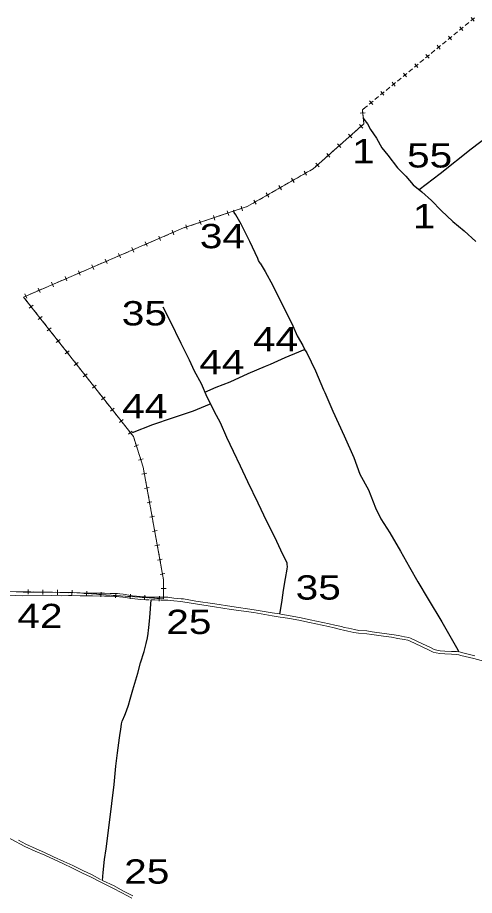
# Model space of a CAD drawing. Extents: x 476989 to 498418, y 4381813 to 4416555.
# Drawn here: x 484730 to 485670, y 4387137 to 4388943 of the extents above; entities that cross this region are included whole.
import ezdxf
from ezdxf.enums import TextEntityAlignment as Align

# ---------------------------------------------------------------- set-up
doc = ezdxf.new("R2010")
doc.units = 0
doc.header["$LTSCALE"] = 20
for name, color, linetype, lineweight in [('13', 7, 'Continuous', 13), ('34', 7, 'Continuous', 13), ('36', 7, 'Continuous', 13), ('6', 7, 'Continuous', 25)]:
    doc.layers.add(name, color=color, linetype=linetype, lineweight=lineweight)

msp = doc.modelspace()

# ---------------------------------------------------------------- linework, layer by layer
at = {"layer": '34'}
for p, q in [((485661.86, 4388935.9), (485669.59, 4388942.24)), ((485662.56, 4388942.93), (485668.9, 4388935.2)), ((485638.68, 4388916.87), (485646.41, 4388923.22)), ((485639.37, 4388923.91), (485645.72, 4388916.18)), ((485650.28, 4388926.39), (485658.01, 4388932.73)), ((485615.5, 4388897.85), (485623.23, 4388904.19)), ((485616.19, 4388904.88), (485622.54, 4388897.15)), ((485627.09, 4388907.36), (485634.82, 4388913.71)), ((485592.32, 4388878.82), (485600.05, 4388885.16)), ((485593.01, 4388885.86), (485599.35, 4388878.13)), ((485603.91, 4388888.34), (485611.64, 4388894.68)), ((485569.13, 4388859.8), (485576.86, 4388866.14)), ((485569.83, 4388866.83), (485576.17, 4388859.1)), ((485580.73, 4388869.31), (485588.46, 4388875.66)), ((485545.95, 4388840.77), (485553.68, 4388847.11)), ((485546.64, 4388847.81), (485552.99, 4388840.08)), ((485557.55, 4388850.29), (485565.28, 4388856.63)), ((485522.77, 4388821.75), (485530.5, 4388828.09)), ((485523.46, 4388828.78), (485529.8, 4388821.05)), ((485534.36, 4388831.26), (485542.09, 4388837.6)), ((485511.18, 4388812.24), (485518.91, 4388818.58)), ((485488, 4388793.21), (485495.73, 4388799.55)), ((485499.58, 4388802.72), (485507.31, 4388809.06)), ((485500.28, 4388809.76), (485506.62, 4388802.03)), ((485464.81, 4388774.19), (485472.54, 4388780.53)), ((485476.4, 4388783.69), (485484.13, 4388790.04)), ((485477.09, 4388790.73), (485483.44, 4388783)), ((485441.63, 4388755.16), (485444.8, 4388757.76)), ((485444.8, 4388757.76), (485449.36, 4388761.5)), ((485453.22, 4388764.67), (485460.95, 4388771.01)), ((485453.91, 4388771.71), (485460.26, 4388763.98)), ((485434.71, 4388745.92), (485444.65, 4388746.95)), ((485440.19, 4388741.47), (485439.16, 4388751.41)), ((485432.69, 4388715.76), (485440.18, 4388722.39)), ((485433.12, 4388722.82), (485439.75, 4388715.33)), ((485441.74, 4388726.56), (485440.71, 4388736.5)), ((485410.23, 4388695.89), (485417.72, 4388702.52)), ((485410.66, 4388702.95), (485417.28, 4388695.46)), ((485421.46, 4388705.83), (485428.95, 4388712.46)), ((485399, 4388685.96), (485406.49, 4388692.59)), ((485376.54, 4388666.09), (485384.03, 4388672.72)), ((485387.76, 4388676.02), (485395.25, 4388682.65)), ((485388.2, 4388683.08), (485394.82, 4388675.59)), ((485354.07, 4388646.22), (485361.56, 4388652.85)), ((485365.3, 4388656.15), (485372.79, 4388662.78)), ((485365.73, 4388663.21), (485372.36, 4388655.72)), ((485342.84, 4388636.28), (485350.33, 4388642.91)), ((485343.27, 4388643.34), (485349.9, 4388635.85)), ((485293.42, 4388612.2), (485298.4, 4388603.52)), ((485304.59, 4388612.84), (485313.26, 4388617.81)), ((485317.59, 4388620.29), (485326.26, 4388625.27)), ((485319.44, 4388627.12), (485324.41, 4388618.44)), ((485265.56, 4388590.45), (485274.23, 4388595.43)), ((485267.41, 4388597.28), (485272.38, 4388588.6)), ((485278.57, 4388597.92), (485287.25, 4388602.89)), ((485291.58, 4388605.37), (485300.25, 4388610.35)), ((485239.54, 4388575.53), (485248.22, 4388580.51)), ((485241.39, 4388582.36), (485246.37, 4388573.68)), ((485252.56, 4388583), (485261.23, 4388587.97)), ((485213.53, 4388560.61), (485222.2, 4388565.59)), ((485215.38, 4388567.44), (485220.35, 4388558.76)), ((485226.54, 4388568.08), (485235.22, 4388573.05)), ((485157.74, 4388539.13), (485167.22, 4388542.32)), ((485160.89, 4388545.47), (485164.07, 4388535.99)), ((485171.96, 4388543.91), (485181.44, 4388547.09)), ((485186.17, 4388548.68), (485195.65, 4388551.87)), ((485189.32, 4388555.02), (485192.5, 4388545.54)), ((485100.88, 4388520.04), (485110.36, 4388523.22)), ((485104.03, 4388526.37), (485107.21, 4388516.89)), ((485115.1, 4388524.81), (485124.58, 4388528)), ((485129.31, 4388529.59), (485138.79, 4388532.77)), ((485132.46, 4388535.92), (485135.64, 4388526.44)), ((485143.53, 4388534.36), (485153.01, 4388537.55)), ((485047.48, 4388505.3), (485051.45, 4388496.11)), ((485058.65, 4388504.67), (485067.83, 4388508.63)), ((485072.45, 4388510.49), (485081.93, 4388513.67)), ((485075.6, 4388516.82), (485078.79, 4388507.34)), ((485086.67, 4388515.26), (485096.15, 4388518.45)), ((485003.58, 4388480.9), (485012.76, 4388484.86)), ((485017.34, 4388486.84), (485026.52, 4388490.8)), ((485019.95, 4388493.41), (485023.91, 4388484.23)), ((485031.11, 4388492.78), (485040.29, 4388496.75)), ((485044.87, 4388498.72), (485054.05, 4388502.69)), ((484962.27, 4388463.07), (484971.45, 4388467.03)), ((484964.88, 4388469.64), (484968.84, 4388460.46)), ((484976.04, 4388469.01), (484985.22, 4388472.98)), ((484989.8, 4388474.95), (484998.99, 4388478.92)), ((484992.41, 4388481.53), (484996.38, 4388472.35)), ((484920.97, 4388445.25), (484930.15, 4388449.21)), ((484934.73, 4388451.19), (484943.92, 4388455.15)), ((484937.34, 4388457.76), (484941.31, 4388448.58)), ((484948.51, 4388457.13), (484957.69, 4388461.09)), ((484879.66, 4388427.42), (484888.85, 4388431.38)), ((484882.27, 4388433.99), (484886.24, 4388424.81)), ((484893.44, 4388433.36), (484902.62, 4388437.32)), ((484907.2, 4388439.3), (484916.38, 4388443.26)), ((484909.81, 4388445.87), (484913.77, 4388436.69)), ((484838.37, 4388409.59), (484847.55, 4388413.56)), ((484852.13, 4388415.53), (484861.31, 4388419.5)), ((484854.74, 4388422.11), (484858.7, 4388412.92)), ((484865.9, 4388421.48), (484875.08, 4388425.44)), ((484797.06, 4388391.76), (484806.24, 4388395.73)), ((484799.67, 4388398.34), (484803.63, 4388389.16)), ((484810.83, 4388397.71), (484820.01, 4388401.67)), ((484824.6, 4388403.65), (484833.78, 4388407.61)), ((484827.2, 4388410.22), (484831.17, 4388401.04)), ((484755.76, 4388373.94), (484764.94, 4388377.9)), ((484769.53, 4388379.88), (484778.71, 4388383.84)), ((484772.13, 4388386.45), (484776.1, 4388377.27)), ((484783.3, 4388385.82), (484792.48, 4388389.79)), ((484742, 4388368), (484751.17, 4388371.96)), ((484744.6, 4388374.57), (484748.56, 4388365.39)), ((484745.09, 4388364.07), (484751.28, 4388356.22)), ((484753.54, 4388345.27), (484761.39, 4388351.45)), ((484754.37, 4388352.29), (484760.56, 4388344.43)), ((484763.65, 4388340.5), (484769.84, 4388332.65)), ((484772.1, 4388321.7), (484779.95, 4388327.88)), ((484772.93, 4388328.72), (484779.12, 4388320.86)), ((484782.21, 4388316.93), (484788.4, 4388309.08)), ((484790.66, 4388298.13), (484798.52, 4388304.31)), ((484791.49, 4388305.15), (484797.68, 4388297.29)), ((484800.77, 4388293.36), (484806.96, 4388285.51)), ((484809.22, 4388274.56), (484817.08, 4388280.74)), ((484810.05, 4388281.58), (484816.24, 4388273.72)), ((484819.33, 4388269.79), (484825.52, 4388261.94)), ((484827.78, 4388250.99), (484835.64, 4388257.17)), ((484828.61, 4388258.01), (484834.8, 4388250.15)), ((484837.89, 4388246.22), (484844.08, 4388238.37)), ((484846.34, 4388227.42), (484854.2, 4388233.6)), ((484847.17, 4388234.44), (484853.36, 4388226.58)), ((484856.45, 4388222.65), (484862.64, 4388214.8)), ((484864.9, 4388203.85), (484872.76, 4388210.03)), ((484865.73, 4388210.87), (484871.92, 4388203.01)), ((484875.01, 4388199.08), (484881.2, 4388191.23)), ((484883.46, 4388180.28), (484891.32, 4388186.46)), ((484884.29, 4388187.3), (484890.48, 4388179.44)), ((484893.57, 4388175.52), (484899.76, 4388167.66)), ((484902.02, 4388156.71), (484909.88, 4388162.9)), ((484902.85, 4388163.73), (484909.04, 4388155.87)), ((484912.13, 4388151.95), (484918.32, 4388144.09)), ((484920.58, 4388133.14), (484928.44, 4388139.33)), ((484921.41, 4388140.16), (484927.6, 4388132.3)), ((484930.69, 4388128.38), (484936.88, 4388120.52)), ((484939.14, 4388109.57), (484947, 4388115.76)), ((484939.97, 4388116.59), (484946.16, 4388108.73)), ((484949.25, 4388104.81), (484955.44, 4388096.95)), ((484957.7, 4388086), (484965.56, 4388092.19)), ((484958.53, 4388093.02), (484964.72, 4388085.16)), ((484969.19, 4388060.71), (484978.73, 4388063.74)), ((484972.45, 4388066.99), (484975.47, 4388057.46)), ((484976.99, 4388052.69), (484980.01, 4388043.16)), ((484978.27, 4388032.12), (484987.8, 4388035.14)), ((484981.52, 4388038.4), (484984.55, 4388028.87)), ((484985.5, 4388003.73), (484995.34, 4388005.51)), ((484989.53, 4388009.54), (484991.31, 4387999.7)), ((484992.2, 4387994.78), (484993.99, 4387984.94)), ((484994.88, 4387980.02), (484996.66, 4387970.18)), ((484990.85, 4387974.21), (485000.69, 4387975.99)), ((484997.55, 4387965.26), (484999.33, 4387955.42)), ((484996.19, 4387944.69), (485006.03, 4387946.47)), ((485000.22, 4387950.5), (485002, 4387940.66)), ((485002.89, 4387935.74), (485004.67, 4387925.9)), ((485001.54, 4387915.17), (485011.38, 4387916.95)), ((485005.56, 4387920.98), (485007.35, 4387911.14)), ((485008.24, 4387906.22), (485010.02, 4387896.38)), ((485010.91, 4387891.46), (485012.69, 4387881.62)), ((485006.88, 4387885.65), (485016.72, 4387887.43)), ((485013.58, 4387876.7), (485015.36, 4387866.86)), ((485012.22, 4387856.13), (485022.06, 4387857.91)), ((485016.25, 4387861.94), (485018.03, 4387852.1)), ((485018.92, 4387847.18), (485020.71, 4387837.34)), ((485017.57, 4387826.61), (485027.41, 4387828.39)), ((485021.6, 4387832.42), (485023.38, 4387822.58)), ((485024.27, 4387817.66), (485026.05, 4387807.82)), ((485022.91, 4387797.09), (485032.75, 4387798.87)), ((485026.94, 4387802.9), (485028.72, 4387793.06)), ((484751.71, 4387766.39), (484751.56, 4387756.4)), ((484781.71, 4387765.94), (484781.55, 4387755.94)), ((484811.7, 4387765.48), (484811.55, 4387755.48)), ((484841.7, 4387765.02), (484841.55, 4387755.02)), ((484871.9, 4387763), (484871.21, 4387753.03)), ((485025, 4387768.17), (485035, 4387768.17)), ((485030, 4387773.17), (485030, 4387763.17)), ((484741.63, 4387761.55), (484731.64, 4387761.7)), ((484756.63, 4387761.32), (484746.63, 4387761.47)), ((484771.63, 4387761.09), (484761.63, 4387761.24)), ((484786.63, 4387760.86), (484776.63, 4387761.01)), ((484801.63, 4387760.63), (484791.63, 4387760.78)), ((484816.63, 4387760.4), (484806.63, 4387760.56)), ((484831.62, 4387760.17), (484821.62, 4387760.33)), ((484861.58, 4387758.71), (484851.6, 4387759.4)), ((484876.54, 4387757.67), (484866.57, 4387758.36)), ((484891.5, 4387756.63), (484881.53, 4387757.32)), ((484906.47, 4387755.59), (484896.49, 4387756.28)), ((484901.83, 4387760.92), (484901.13, 4387750.95)), ((484921.43, 4387754.55), (484911.46, 4387755.24)), ((484936.4, 4387753.51), (484926.42, 4387754.2)), ((484931.76, 4387758.84), (484931.06, 4387748.87)), ((484951.36, 4387752.47), (484941.38, 4387753.16)), ((484966.32, 4387751.43), (484956.35, 4387752.12)), ((484961.68, 4387756.76), (484960.99, 4387746.79)), ((484981.29, 4387750.39), (484971.31, 4387751.08)), ((484996.25, 4387749.35), (484986.28, 4387750.04)), ((484991.61, 4387754.68), (484990.92, 4387744.7)), ((485011.22, 4387748.31), (485001.24, 4387749)), ((485026.18, 4387747.27), (485016.2, 4387747.96)), ((485021.54, 4387752.6), (485020.85, 4387742.62)), ((485030, 4387758.17), (485030, 4387748.17))]:
    msp.add_line(p, q, dxfattribs=at)
for points in [[(484742, 4388368), (485071, 4388510), (485202, 4388554), (485338, 4388632), (485442, 4388724), (485439, 4388753), (485444.8, 4388757.76)], [(485330.6, 4388627.76), (485338, 4388632), (485339.1, 4388632.98)], [(485200.39, 4388553.46), (485202, 4388554), (485209.2, 4388558.13)], [(484742, 4388368), (484968, 4388081), (484988, 4388018), (485030, 4387786), (485030, 4387747), (484843, 4387760), (484712, 4387762), (484623, 4387793), (484342, 4387807), (484273, 4387819), (484108.44, 4387807.03)], [(484967.81, 4388081.24), (484968, 4388081), (484970.93, 4388071.76)], [(484986.06, 4388024.1), (484988, 4388018), (484988.64, 4388014.46)], [(485029.61, 4387788.14), (485030, 4387786), (485030, 4387778.17)], [(484846.61, 4387759.75), (484843, 4387760), (484836.62, 4387760.1)]]:
    msp.add_lwpolyline(points, dxfattribs=at)
at = {"layer": '36'}
for points in [[(484798.95, 4387753.61), (484740.73, 4387753.43), (484711.52, 4387754.84), (484691.22, 4387758.64), (484678.76, 4387763.13), (484663.74, 4387768.84), (484653.58, 4387774.86), (484642.8, 4387780.89), (484632.55, 4387784.9), (484626.77, 4387786.76), (484614.38, 4387788.44), (484579.29, 4387793.34), (484491.86, 4387799.73)], [(484798.93, 4387760.7), (484740.89, 4387760.52), (484712.35, 4387761.9), (484693.08, 4387765.5), (484681.23, 4387769.77), (484666.83, 4387775.25), (484657.12, 4387781), (484645.83, 4387787.32), (484634.93, 4387791.59), (484628.34, 4387793.7), (484615.13, 4387795.49), (484580.58, 4387800.8), (484492.14, 4387806.72)], [(484798.93, 4387760.7), (484834.03, 4387759.68), (484840.94, 4387759.89), (484858.69, 4387759.43), (484883.86, 4387758.86), (484908.49, 4387758.47), (484919.79, 4387758.31), (484929.83, 4387758.04), (484934.93, 4387757.78), (484940.17, 4387757.35), (484946.81, 4387756.64), (484966.32, 4387753.46), (484982.82, 4387751.87), (484993.84, 4387750.94), (485001.08, 4387750.58), (485011.81, 4387750.66), (485025.45, 4387750.29), (485038.89, 4387750.19), (485051.42, 4387748.65), (485066.32, 4387747.42), (485070.86, 4387746.77), (485096.5, 4387742.28), (485135.5, 4387736.71), (485170.14, 4387731.03), (485216.24, 4387724.72), (485253.12, 4387718.26), (485268.79, 4387715.93), (485270.96, 4387715.52), (485290.18, 4387712.13), (485309.62, 4387708.84), (485331.43, 4387704.04), (485370.49, 4387695.9), (485382.54, 4387692.96), (485395.76, 4387690.01), (485401.7, 4387688.38), (485410.35, 4387686.48), (485422.59, 4387683.93), (485431.58, 4387682.19), (485448.2, 4387681.05)], [(484798.95, 4387753.61), (484820.12, 4387753.58), (484834.17, 4387753.81), (484840.95, 4387754.01), (484858.55, 4387753.56), (484883.74, 4387752.99), (484908.41, 4387752.6), (484919.67, 4387752.44), (484929.6, 4387752.17), (484934.54, 4387751.92), (484939.61, 4387751.5), (484946.03, 4387750.81), (484965.57, 4387747.63), (484982.29, 4387746.02), (484993.45, 4387745.08), (485000.69, 4387744.72)], [(485004.65, 4387744.73), (485011.76, 4387744.78), (485025.35, 4387744.41), (485038.51, 4387744.32), (485050.82, 4387742.8), (485065.65, 4387741.58), (485069.93, 4387740.96), (485095.58, 4387736.47), (485134.61, 4387730.9), (485169.26, 4387725.22), (485215.38, 4387718.9), (485253.12, 4387712.35), (485269.91, 4387709.7), (485276.03, 4387708.96), (485289.33, 4387706.75), (485308.29, 4387703.12), (485330.2, 4387698.29), (485369.19, 4387690.16), (485381.21, 4387687.24), (485394.34, 4387684.31), (485400.29, 4387682.67), (485409.12, 4387680.73), (485421.43, 4387678.16), (485430.75, 4387676.36), (485448.2, 4387675.12)], [(485448.2, 4387681.05), (485458.98, 4387679.52), (485483.62, 4387676.09), (485499.96, 4387673.83), (485513.05, 4387671.47), (485525.85, 4387669.03), (485534.71, 4387667.62), (485537.94, 4387666.38), (485539.28, 4387665.58), (485561.41, 4387655.37), (485580.28, 4387646.32), (485586.96, 4387643.16), (485592.33, 4387641.73), (485599.42, 4387640.44), (485608.78, 4387639.71), (485622.5, 4387638.98), (485632.69, 4387638.46), (485639.02, 4387637.77), (485643.14, 4387636.43), (485670.12, 4387629.89)], [(485448.2, 4387675.12), (485458.17, 4387673.7), (485482.82, 4387670.27), (485499.03, 4387668.02), (485511.98, 4387665.69), (485524.84, 4387663.24), (485532.77, 4387661.98), (485537.4, 4387660.22), (485559.04, 4387649.99), (485577.75, 4387641.02), (485584.93, 4387637.62), (485591.05, 4387636), (485598.66, 4387634.6), (485608.4, 4387633.84), (485622.19, 4387633.11), (485632.22, 4387632.6), (485637.78, 4387631.99), (485641.54, 4387630.77), (485668.67, 4387624.2), (485701.31, 4387615.39)], [(484660.3, 4387281.08), (484688, 4387267.44), (484716.6, 4387252.46), (484744.57, 4387237.87), (484765.96, 4387228.04), (484785.95, 4387219.5), (484804.94, 4387211.05), (484823.92, 4387201.9), (484841.33, 4387193.76), (484861.92, 4387183.47), (484880.95, 4387174.47), (484900.92, 4387163.88), (484925.9, 4387151.85), (484944.1, 4387141.99), (484964.47, 4387131.61)], [(484731.26, 4387250.54), (484746.8, 4387242.43), (484768.02, 4387232.68), (484785.12, 4387224.95), (484803.58, 4387216.58), (484824.62, 4387206.9), (484843.61, 4387198.29), (484864.14, 4387188.04), (484883.22, 4387179.01), (484900.49, 4387169.86)], [(484904.27, 4387167.9), (484928.21, 4387156.37), (484946.46, 4387146.48), (484966.73, 4387136.15)]]:
    msp.add_lwpolyline(points, dxfattribs=at)
at = {"layer": '6'}
for points in [[(485556.22, 4388588.91), (485598.98, 4388622.45), (485662.95, 4388672.73), (485708.55, 4388708.04), (485754.62, 4388742.62), (485772.47, 4388756.23)], [(485440.7, 4388737.5), (485441.99, 4388734.08), (485449.36, 4388724.07), (485456.08, 4388712.46), (485468.1, 4388694.6), (485479.36, 4388675.04), (485491.14, 4388660.05), (485511.34, 4388633.52), (485528.76, 4388616.39), (485543.57, 4388599.11), (485561.47, 4388584.67), (485581.34, 4388566.46), (485601.43, 4388546.21), (485625.33, 4388523.43), (485648.4, 4388503.95), (485672.73, 4388482.48)], [(485224.04, 4388447.11), (485207.78, 4388482.2), (485189.48, 4388517.58), (485178.95, 4388536.92), (485175.21, 4388541.77), (485174.76, 4388545.72), (485175.43, 4388546.79)], [(485228.46, 4388437.56), (485225.43, 4388443.22), (485224.04, 4388447.11)], [(485228.44, 4388437.61), (485239.13, 4388420.45), (485254.49, 4388392.02), (485266.8, 4388367.49), (485283.36, 4388333.76), (485295.91, 4388308.62), (485304.83, 4388288.39), (485316.35, 4388267.98), (485320.79, 4388259.19)], [(485028.24, 4388347.65), (485043.19, 4388319.65), (485065.47, 4388273.4), (485082.48, 4388238.78), (485092.64, 4388215.91), (485107.46, 4388190.21), (485118.68, 4388162.55), (485126.48, 4388148.04)], [(485249.87, 4388230.09), (485280.42, 4388243.58), (485308.34, 4388255.24), (485317.7, 4388259.03), (485319.71, 4388259.39), (485321.11, 4388258.63), (485322.2, 4388257.5), (485324.66, 4388253.42), (485342.55, 4388215.99), (485359.1, 4388177.28), (485361.75, 4388171.57)], [(485114.58, 4388171.97), (485138.19, 4388182.42), (485167.22, 4388193.28), (485204.15, 4388210.77), (485239.57, 4388225.59), (485250.04, 4388230.2)], [(485361.68, 4388171.46), (485378.46, 4388133.46), (485401.8, 4388082.2), (485421.34, 4388037.69), (485434.11, 4388003.69), (485451.8, 4387971.36), (485466.24, 4387934.48), (485477.35, 4387911.58), (485495.47, 4387882.54), (485517.79, 4387845.13), (485536.33, 4387812.23), (485553.28, 4387782.16)], [(484965.74, 4388089.59), (485008.16, 4388105.83), (485048.14, 4388119.54), (485091.39, 4388133.96), (485124.78, 4388147.26), (485126.61, 4388148.09)], [(485126.61, 4388148.09), (485133.89, 4388132.19), (485146.45, 4388109.63), (485159.7, 4388079.42), (485173.4, 4388051.16), (485187.78, 4388020.66), (485202.68, 4387988.5), (485223.68, 4387944.5), (485241.45, 4387906.87), (485258.16, 4387874.34), (485274.72, 4387839.19), (485283.44, 4387821.96), (485283.82, 4387817.85), (485284.05, 4387813.43), (485283.91, 4387808.34), (485279.89, 4387789.2)], [(485279.89, 4387789.2), (485276.31, 4387764.85), (485273.22, 4387744.39), (485270.15, 4387723.13), (485268.79, 4387715.93)], [(485553.28, 4387782.16), (485574.6, 4387746.28), (485602.45, 4387699.59), (485635.65, 4387642.16), (485636.43, 4387640.27), (485636.65, 4387638.03)], [(484904.27, 4387167.9), (484905.66, 4387183.86), (484908.57, 4387210.82), (484911.66, 4387232.66), (484916.02, 4387264.71), (484923.85, 4387325.72), (484928.6, 4387365.22), (484931.97, 4387402.9), (484935.53, 4387430.32), (484939.12, 4387461.07), (484940.92, 4387470.98), (484942.02, 4387478.39), (484943.44, 4387490.05), (484944.88, 4387495.32), (484945.51, 4387496.66), (484950.42, 4387507.8), (484953.76, 4387516.7), (484957.52, 4387528.13), (484961.56, 4387540.98), (484966.88, 4387559.67), (484976.87, 4387594.07), (484982.74, 4387615.17), (484989.84, 4387639.07), (484994.09, 4387655.51), (484996.91, 4387666.98), (484998.31, 4387675.88), (484999.26, 4387682.75), (484999.77, 4387687.23), (485001.75, 4387708.92), (485004.65, 4387744.73)]]:
    msp.add_lwpolyline(points, dxfattribs=at)

# ---------------------------------------------------------------- texts
at = {"layer": '13', "width": 1.25}
for s, p in [('34', (485151.06, 4388468.36)), ('35', (484990.5, 4388309.57)), ('44', (485260.34, 4388256.07)), ('44', (485149.96, 4388209.26)), ('44', (484991.33, 4388118.37)), ('35', (485348.25, 4387745.52)), ('42', (484775.6, 4387686.81)), ('25', (485081.99, 4387674.67)), ('25', (484995.38, 4387161.14))]:
    msp.add_text(s, height=50, dxfattribs=at).set_placement(p, align=Align.CENTER)
at = {"layer": '6', "width": 1.25}
for s, p in [('1', (485441.14, 4388643)), ('55', (485577.39, 4388634.42)), ('1', (485565.93, 4388509.28))]:
    msp.add_text(s, height=50, dxfattribs=at).set_placement(p, align=Align.CENTER)

doc.saveas('drawing.dxf')
